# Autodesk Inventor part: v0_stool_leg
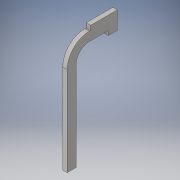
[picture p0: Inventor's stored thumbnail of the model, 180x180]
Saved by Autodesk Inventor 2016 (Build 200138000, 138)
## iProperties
Created: 2015-07
Part Number: v0_stool_leg
Material: Generic
Document SubType Name: Modeling
Designer: t_patrw
Density: 1 g/cm^3
Appearance: Default
Author: t_patrw
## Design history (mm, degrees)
sketch "Sketch1"
  geometry: L1 (-18.288, 139.606)-(-18.288, 25.306); L2 (-91.44, 212.758)-(-457.2, 212.758); L3 (-457.2, 231.046)-(-91.44, 231.046); L4 (0, 139.606)-(0, 25.306); L5 (-36.576, 25.306)-(-36.576, 139.606); L6 (-91.44, 194.47)-(-457.2, 194.47); L7 (-457.2, 231.046)-(-457.2, 194.47); L8 (0, 25.306)-(-36.576, 25.306); L9 (-36.576, 25.306)-(-54.864, 25.306); L10 (-54.864, 25.306)-(-54.864, 61.882); L11 (-54.864, 61.882)-(-36.576, 61.882); L12 (0, 25.306)-(18.288, 25.306); L13 (18.288, 25.306)-(18.288, 135.034); L14 (18.288, 135.034)-(0, 135.034); A1 r 73.152 centre (-91.44, 139.606) between (-18.288, 139.606) and (-91.44, 212.758); A2 r 91.44 centre (-91.44, 139.606) between (0, 139.606) and (-91.44, 231.046); A3 r 54.864 centre (-91.44, 139.606) between (-36.576, 139.606) and (-91.44, 194.47); 1 further point
  constraints: 28 end point, 6 point on circle, 5 perpendicular, 3 centre point, 3 horizontal, 2 point on line, 2 vertical, 1 parallel, 4 other
  dimensions: "d3" = 73.152 horizontal distance of L1.start L2.start (= 4 x Thickness); "d4" = 73.152 horizontal distance of L2.start L1.start (= 4 x Thickness); "d6" = 73.152 radius of A1 (= 4 x Thickness); "d7" = 18.288 distance from line of point (0, 0) L1 (= Thickness); "d8" = 457.2 horizontal distance of point (0, 0) L2.end (= Height); "d9" = 18.288 radial gap between concentric circles of A1 A2 (= Thickness); "d10" = 18.288 distance between parallel lines of L1 L5 (= Thickness); "d13" = 114.3 distance of L1.start L1.end; "d14" = 36.576 distance of L9.end L10.end (= 2 x Thickness); "d15" = 18.288 distance of L5.start L9.end (= Thickness); "d16" = 18.288 distance of L4.end L12.end (= Thickness); "d17" = 109.728 distance of L12.end L13.end (= 6 x Thickness)
extrude "Extrusion1" new body sketch "Sketch1" distance "d11" = 18.288 (= Thickness); taper "d12" = 0 deg
body "Solid1"
other parameters: "Thickness" = 18.288 [user parameter; used in 11 equation terms], "Height" = 457.2 [user parameter; used in 1 equation term], "Seat_Diameter" = 381 [user parameter]
